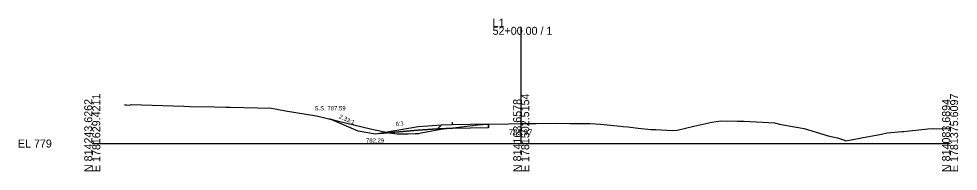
# Model space of a CAD drawing. Extents: x 5574 to 10203, y -10 to 9546.
# Drawn here: x 5574.3 to 5902.8, y 8990.3 to 9043.7 of the extents above; entities that cross this region are included whole.
import ezdxf

# ---------------------------------------------------------------- set-up
doc = ezdxf.new("R2010")
doc.units = 0
for name, color, linetype in [('Exist Cross Section Cell', 7, 'Continuous'), ('Exist XS Center Line Elevation Label', 7, 'Continuous'), ('Exist XS Ground Line', 7, 'Continuous'), ('Prop XS Ditch Slope Text', 7, 'Continuous'), ('Prop XS Ditch Standard Text', 7, 'Continuous'), ('Prop XS Dump Level', 7, 'Continuous'), ('Prop XS Earthwork Shape', 7, 'Continuous'), ('Prop XS EOT Tick Mark', 7, 'Continuous'), ('Prop XS Finish Grade', 7, 'Continuous'), ('Prop XS Finish Grade Earthwork', 7, 'Continuous'), ('Prop XS Finish Grade Paved Shoulder', 7, 'Continuous'), ('Prop XS Finish Grade Pavement', 7, 'Continuous'), ('Prop XS Hydro Typical Ditch Data', 7, 'Continuous'), ('Prop XS Pvmt Edge Slope', 7, 'Continuous'), ('Prop XS Side Slope Text', 7, 'Continuous'), ('Prop XS SS Elevation Text', 7, 'Continuous'), ('Prop XS Subgrade Earthwork', 7, 'Continuous'), ('Scratch_Level_3', 7, 'Continuous'), ('Scratch_Level_6', 7, 'Continuous')]:
    doc.layers.add(name, color=color, linetype=linetype)

msp = doc.modelspace()

# ---------------------------------------------------------------- linework, layer by layer
at = {"layer": 'Exist Cross Section Cell'}
for p, q in [((5750, 9000), (5750, 9040.86)), ((5600, 9000), (5750, 9000)), ((5750, 9000), (5900, 9000))]:
    msp.add_line(p, q, dxfattribs=at)
at = {"layer": 'Exist XS Ground Line'}
for p, q in [((5611.3, 9013.55), (5611.98, 9013.56)), ((5611.98, 9013.56), (5612.99, 9013.47)), ((5612.99, 9013.47), (5613.58, 9013.62)), ((5613.58, 9013.62), (5631.97, 9013.04)), ((5631.97, 9013.04), (5634.17, 9012.98)), ((5634.17, 9012.98), (5642.71, 9012.81)), ((5642.71, 9012.81), (5646.77, 9012.73)), ((5646.77, 9012.73), (5647.53, 9012.72)), ((5647.53, 9012.72), (5648.26, 9012.7)), ((5648.26, 9012.7), (5662.71, 9012.35)), ((5662.71, 9012.35), (5667.61, 9011.46)), ((5667.61, 9011.46), (5678.39, 9009.68)), ((5678.39, 9009.68), (5685.68, 9007.96)), ((5685.68, 9007.96), (5697.83, 9005.03)), ((5721.96, 9005), (5723.9, 9005.23)), ((5723.9, 9005.23), (5727.28, 9005.64)), ((5727.28, 9005.64), (5734.81, 9006.56)), ((5734.81, 9006.56), (5736.43, 9006.64)), ((5736.43, 9006.64), (5738.53, 9006.75)), ((5738.53, 9006.75), (5745.55, 9006.88)), ((5745.55, 9006.88), (5750, 9006.97)), ((5750, 9006.97), (5750.5, 9006.98)), ((5750.5, 9006.98), (5755.19, 9007.03)), ((5755.19, 9007.03), (5761.87, 9007.12)), ((5761.87, 9007.12), (5767.19, 9007.06)), ((5767.19, 9007.06), (5774.06, 9006.96)), ((5774.06, 9006.96), (5776.02, 9006.86)), ((5776.02, 9006.86), (5777.73, 9006.78)), ((5777.73, 9006.78), (5784.68, 9006.1)), ((5784.68, 9006.1), (5785.66, 9005.97)), ((5785.66, 9005.97), (5787.3, 9005.84)), ((5787.3, 9005.84), (5790.89, 9005.4)), ((5790.89, 9005.4), (5795.49, 9004.96)), ((5804.57, 9004.73), (5807.42, 9005.43)), ((5807.42, 9005.43), (5810.44, 9006.09)), ((5810.44, 9006.09), (5816.69, 9007.46)), ((5816.69, 9007.46), (5818.24, 9007.73)), ((5818.24, 9007.73), (5819.92, 9007.9)), ((5819.92, 9007.9), (5825.65, 9007.87)), ((5825.65, 9007.87), (5827.99, 9007.87)), ((5827.99, 9007.87), (5834.44, 9007.44)), ((5834.44, 9007.44), (5838.61, 9007.24)), ((5838.61, 9007.24), (5840.35, 9006.8)), ((5840.35, 9006.8), (5845.6, 9005.81)), ((5845.6, 9005.81), (5848.94, 9005.31)), ((5848.94, 9005.31), (5857.41, 9002.75)), ((5891.16, 9005.04), (5892.26, 9005.1)), ((5892.26, 9005.1), (5894.17, 9005.22)), ((5894.17, 9005.22), (5900, 9005.15)), ((5697.83, 9005.03), (5703.45, 9003.82)), ((5703.45, 9003.82), (5706.6, 9003.45)), ((5706.6, 9003.45), (5708.1, 9003.44)), ((5708.1, 9003.44), (5710.48, 9003.38)), ((5710.48, 9003.38), (5712.89, 9003.53)), ((5712.89, 9003.53), (5714.19, 9003.54)), ((5714.19, 9003.54), (5715.06, 9003.7)), ((5715.06, 9003.7), (5721.96, 9005)), ((5795.49, 9004.96), (5797.09, 9004.87)), ((5797.09, 9004.87), (5802.75, 9004.57)), ((5802.75, 9004.57), (5804.57, 9004.73)), ((5857.41, 9002.75), (5860.6, 9001.95)), ((5860.6, 9001.95), (5863.11, 9001.13)), ((5865.39, 9001.29), (5869.07, 9001.96)), ((5869.07, 9001.96), (5876, 9003.26)), ((5876, 9003.26), (5878.05, 9003.75)), ((5878.05, 9003.75), (5883.26, 9004.18)), ((5883.26, 9004.18), (5883.8, 9004.22)), ((5883.8, 9004.22), (5884.75, 9004.33)), ((5884.75, 9004.33), (5891.16, 9005.04)), ((5863.11, 9001.13), (5863.59, 9000.98)), ((5863.59, 9000.98), (5864.04, 9001.08)), ((5864.04, 9001.08), (5865.39, 9001.29))]:
    msp.add_line(p, q, dxfattribs=at)
at = {"layer": 'Prop XS Dump Level'}
msp.add_line((5738.54, 9006.74), (5726, 9006.49), dxfattribs=at)
msp.add_line((5738.54, 9006.74), (5726, 9006.49), dxfattribs=at)
at = {"layer": 'Prop XS Earthwork Shape'}
for points in [[(5693, 9004.29), (5683, 9008.59), (5685.68, 9007.96), (5697.83, 9005.03), (5703.45, 9003.82), (5703.7, 9003.79), (5700.46, 9003.53), (5699, 9003.29)], [(5714, 9004.62), (5703.7, 9003.79), (5706.6, 9003.45), (5708.1, 9003.44), (5710.48, 9003.38), (5712.89, 9003.53), (5714.19, 9003.54), (5715.06, 9003.7), (5721.96, 9005), (5723.81, 9005.22), (5722, 9005.18), (5720.72, 9005.15), (5719, 9005.02)], [(5726, 9005.26), (5723.81, 9005.22), (5723.9, 9005.23), (5727.28, 9005.64), (5734.81, 9006.56), (5736.43, 9006.64), (5738.53, 9006.75), (5738.55, 9006.75), (5738.55, 9005.5)]]:
    msp.add_lwpolyline(points, close=True, dxfattribs=at)
at = {"layer": 'Prop XS EOT Tick Mark'}
msp.add_line((5726, 9006.51), (5726, 9007.51), dxfattribs=at)
at = {"layer": 'Prop XS Finish Grade'}
for p, q in [((5714, 9005.79), (5700.46, 9003.53)), ((5719, 9006.19), (5714, 9005.79)), ((5722, 9006.43), (5719, 9006.19))]:
    msp.add_line(p, q, dxfattribs=at)
at = {"layer": 'Prop XS Finish Grade Earthwork'}
for p, q in [((5693, 9004.29), (5683, 9008.59)), ((5699, 9003.29), (5693, 9004.29)), ((5700.46, 9003.53), (5699, 9003.29))]:
    msp.add_line(p, q, dxfattribs=at)
at = {"layer": 'Prop XS Finish Grade Paved Shoulder'}
msp.add_line((5726, 9006.51), (5722, 9006.43), dxfattribs=at)
at = {"layer": 'Prop XS Finish Grade Pavement'}
msp.add_line((5738.55, 9006.75), (5726, 9006.51), dxfattribs=at)
at = {"layer": 'Prop XS Hydro Typical Ditch Data'}
for p, q in [((5693, 9004.29), (5683, 9008.59)), ((5714, 9005.79), (5699, 9003.29)), ((5699, 9003.29), (5693, 9004.29))]:
    msp.add_line(p, q, dxfattribs=at)
at = {"layer": 'Prop XS Pvmt Edge Slope'}
msp.add_line((5722, 9006.43), (5720.72, 9005.15), dxfattribs=at)
at = {"layer": 'Prop XS Subgrade Earthwork'}
for p, q in [((5720.72, 9005.15), (5719, 9005.02)), ((5722, 9005.18), (5720.72, 9005.15)), ((5726, 9005.26), (5722, 9005.18)), ((5738.55, 9005.5), (5726, 9005.26)), ((5738.55, 9005.5), (5738.55, 9006.75)), ((5714, 9004.62), (5700.46, 9003.53)), ((5719, 9005.02), (5714, 9004.62))]:
    msp.add_line(p, q, dxfattribs=at)
at = {"layer": 'Scratch_Level_3'}
for p, q in [((5714, 9005.79), (5700.46, 9003.53)), ((5719, 9006.19), (5714, 9005.79)), ((5722, 9006.43), (5719, 9006.19)), ((5719, 9005.02), (5720.72, 9005.15)), ((5720.72, 9005.15), (5722, 9006.43)), ((5700.46, 9003.53), (5714, 9004.62)), ((5714, 9004.62), (5719, 9005.02))]:
    msp.add_line(p, q, dxfattribs=at)
at = {"layer": 'Scratch_Level_6'}
for points in [[(5726, 9005.26), (5723.81, 9005.22), (5723.9, 9005.23), (5727.28, 9005.64), (5734.81, 9006.56), (5736.43, 9006.64), (5738.53, 9006.75), (5738.55, 9006.75), (5738.55, 9005.5)], [(5703.7, 9003.79), (5700.46, 9003.53), (5702.9, 9003.94), (5703.45, 9003.82)]]:
    msp.add_lwpolyline(points, close=True, dxfattribs=at)

# ---------------------------------------------------------------- texts
at = {"layer": 'Exist Cross Section Cell'}
for s, p in [('L1', (5740, 9040.86)), ('52+00.00 / 1', (5740, 9038.06)), ('EL 779', (5574, 8998.6))]:
    msp.add_text(s, height=2.8, dxfattribs=at).set_placement(p)
for s, p in [('N 814243.6262', (5600, 8990)), ('E 1781629.4211', (5602.8, 8990)), ('N 814163.6578', (5750, 8990)), ('E 1781502.5154', (5752.8, 8990)), ('N 814083.6894', (5900, 8990)), ('E 1781375.6097', (5902.8, 8990))]:
    msp.add_text(s, height=2.8, rotation=90, dxfattribs=at).set_placement(p)
at = {"layer": 'Exist XS Center Line Elevation Label'}
msp.add_text('785.97', height=2, dxfattribs=at).set_placement((5745.7, 9002.97))
at = {"layer": 'Prop XS Ditch Slope Text'}
msp.add_text('6:1', height=1.5, rotation=9.4623, dxfattribs=at).set_placement((5706.25, 9006.02))
at = {"layer": 'Prop XS Ditch Standard Text'}
msp.add_text('782.29', height=1.5, dxfattribs=at).set_placement((5695.75, 9000.29))
at = {"layer": 'Prop XS Dump Level'}
for s, height, p in [('Case4', 0.04, (5714, 9005.75)), ('Eop', 0.3, (5738.55, 9006.45))]:
    msp.add_text(s, height=height, dxfattribs=at).set_placement(p)
at = {"layer": 'Prop XS Side Slope Text'}
msp.add_text('2.33:1', height=1.5, rotation=336.7358, dxfattribs=at).set_placement((5686.12, 9008.88))
at = {"layer": 'Prop XS SS Elevation Text'}
msp.add_text('S.S. 787.59', height=1.5, dxfattribs=at).set_placement((5677.78, 9011.59))

doc.saveas('drawing.dxf')
